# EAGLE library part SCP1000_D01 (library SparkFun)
SCP1000 Barometric pressure sensor. Schematic elements and footprint production proven. Spark Fun Electronics SKU : IC-SCP1000-D01
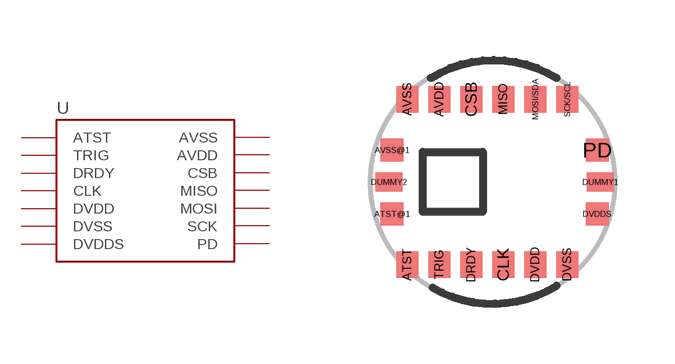
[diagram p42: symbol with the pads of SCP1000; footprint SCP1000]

Designator prefix -

## SCP1000_D01SMD  [SCP1000]
ATST  ATST
AVDD  AVDD
AVSS  AVSS
CLK  CLK
CSB  CSB
DRDY  DRDY
DVDD  DVDD
DVDDS  DVDDS
DVSS  DVSS
MISO  MISO
MOSI/SDA  MOSI
PD  PD
SCK/SCL  SCK
TRIG  TRIG

## Footprint SCP1000 (pad centres in mm)
smd 0.55 x 0.67: ATST -2.135,-2.07; AVDD -1.335,2.07; AVSS -2.135,2.07; CLK 0.265,-2.07; CSB -0.535,2.07; DRDY -0.535,-2.07; DVDD 1.065,-2.07; DVSS 1.865,-2.07; MISO 0.265,2.07; MOSI/SDA 1.065,2.07; SCK/SCL 1.865,2.07; TRIG -1.335,-2.07
smd 0.57 x 0.57: ATST@1 -2.515,-0.8; AVSS@1 -2.515,0.8; DVDDS 2.615,-0.8; PD 2.615,0.8
smd 0.67 x 0.47: DUMMY1 2.695,0; DUMMY2 -2.595,0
